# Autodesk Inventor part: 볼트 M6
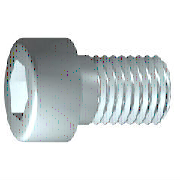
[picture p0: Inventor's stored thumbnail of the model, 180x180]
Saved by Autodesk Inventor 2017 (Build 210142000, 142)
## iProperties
IsCustomPart: 1
Created: 2012-02
Part Number: 볼트 M6
Material: 강철, 연강
Document SubType Name: Modeling
Standard: JIS B 1176
Designer: mdu-01
Standards Organization: JIS
Language: ko-KR
Size Designation: M6 x 16
Categories: <MemberInstance><Categories><Category DisplayName="조임쇠" InternalName="e4da775c-781d-43d5-af7c-5136215cf5a6" Mnemonic="FSTN"><Category DisplayName="볼트" InternalN
Density: 1 g/cm^3
Appearance: 강철
Author: mdu-01
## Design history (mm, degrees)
sketch "스케치1"
  geometry: L1 (-1.333, 0)-(16, 0); L2 (16, 0)-(16, 3); L3 (16, 3)-(2.5, 3); L4 (2.5, 3)-(1.886, 3); L5 (1.886, 3)-(0, 3); L6 (0, 3)-(0, 5); L7 (0, 5)-(-6, 5); L8 (-6, 5)-(-6, 2.887); L9 (-6, 2.887)-(-3, 2.887); L10 (-3, 2.887)-(-1.333, 0); L11 (-10.4, 0)-(20.4, 0) reference; L12 (0, -1)-(0, 6) reference; L13 (2.5, 3)-(0, 3)
  constraints: 22 end point, 6 parallel, 2 collinear, 2 perpendicular, 1 horizontal, 1 point on line
  dimensions: "d1" = 13.5 distance from line of L3.end L2 (= GEL); "d2" = 0.61355 distance of L4.end L3.end (computed from GAL); "d3" = 6 distance between parallel lines of L8 L6 (= KOH); "d4" = 3 distance of L8.end L9.end (= INTI); "d5" = 60 deg angle of L10 L1; "d6" = 6 diameter of L3 L1 (= GD); "d7" = 6 diameter of L5 L1 (= BDM); "d8" = 5.7735 diameter of L9 L1 (= 1.1547 x SW); "d9" = 10 diameter of L7 L1 (= KOD); "d26" = 16 distance between parallel lines of L12 L2 (= NLG)
revolve "본체" sketch "스케치1" stored, may be unused: angle "d10" = 90 deg
sketch "스케치2"
  geometry: L1 (0, -7)-(0, 7) reference; L2 (-7, 0)-(7, 0) reference; L3 (2.887, 0)-(1.443, -2.5); L4 (1.443, -2.5)-(-1.443, -2.5); L5 (-1.443, -2.5)-(-2.887, 0); L6 (-2.887, 0)-(-1.443, 2.5); L7 (-1.443, 2.5)-(1.443, 2.5); L8 (1.443, 2.5)-(2.887, 0); 2 further points
  constraints: 12 end point, 1 coincident, 1 horizontal alignment, 1 point on line, 12 other
extrude "슬롯" join sketch "스케치2" stored distance "d11" = 10; taper "d12" = 0 deg
workplane "Work Plane1"
fillet "Fillet2" dims "d30" = 0.1 (= R)
body "Solid1"
fillet "모깎기1" dims "d17" = 0.6 (= RR)
feature "스레드" dims "d13" = 13.5 (= GEL), "d14" = 0
chamfer "모따기1" distance "d15" = 0.61345 (= -0.5 x SPD + 0.5 x GD); stored, may be unused: second distance "d16" = 0.61345 (= GUL), angle "d27" = 45 deg
other parameters: "GD" = 6 (= NND) [user parameter; used in 2 equation terms], "NLG" = 16 [user parameter; used in 1 equation term], "GEL" = 13.5 [user parameter; used in 2 equation terms], "KOD" = 10 [user parameter; used in 1 equation term], "KOH" = 6 [user parameter; used in 1 equation term], "INTI" = 3 [user parameter; used in 1 equation term], "GAL" = 0.61345 (= 0.61345 x PTC) [user parameter; used in 1 equation term], "GUL" = 0.61345 (= 0.61345 x PTC) [user parameter; used in 1 equation term], "BDM" = 6 (= NND) [user parameter; used in 1 equation term], "SW" = 5 [user parameter; used in 2 equation terms], "RR" = 0.6 [user parameter; used in 1 equation term], "SPD" = 4.7731 (= NND - 1.2269 x PTC) [user parameter; used in 1 equation term], "d19" = 0, "d28" = 0, "d29" = 0, "R" = 0.1 [user parameter; used in 1 equation term], "PHH" = 0.25 [user parameter], "GD1" = 4.7731 (= THREADDIA - 1.2269 x PTC) [user parameter], "THREADDIA" = 6 [user parameter; used in 1 equation term], "FAWI" = 45 deg [user parameter], "PTC" = 1 [user parameter; used in 5 equation terms], "NND" = 6 [user parameter; used in 3 equation terms], "TOA" = 30 deg [user parameter], "E0" = 5.775 (= 1.155 x SW) [user parameter]
